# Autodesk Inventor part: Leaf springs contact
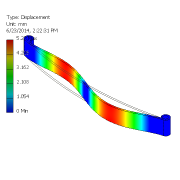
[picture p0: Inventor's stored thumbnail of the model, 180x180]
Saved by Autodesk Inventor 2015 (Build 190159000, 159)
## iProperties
Created: 2013-01
Part Number: Leaf springs contact
Material: Steel, Mild
Document SubType Name: Modeling
Designer: CADCIM
Density: 7.86 g/cm^3
Appearance: Steel
Mass: 9.78337 g
Surface Area: 26.8047 cm^2
Volume: 1.2447 cm^3
Author: CADCIM
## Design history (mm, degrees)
sketch "Sketch1"
  geometry: L1 (-48.188, 1.022)-(-47.141, 0.956); L2 (48.275, 0.799)-(47.214, 0.677); A1 r 200 centre (0, 193.649) between (-50, 0) and (50, 0); A2 r 201.033 centre (0, 193.649) between (-50.258, -1) and (50.258, -1); A3 r 1.5 centre (-49.625, 1.452) between (-48.188, 1.022) and (-50, 0); A4 r 2.533 centre (-49.625, 1.452) between (-47.141, 0.956) and (-50.258, -1); A5 r 1.5 centre (49.625, 1.452) between (50, 0) and (48.275, 0.799); A6 r 2.533 centre (49.625, 1.452) between (50.258, -1) and (47.214, 0.677); 1 further point
  constraints: 12 point on circle, 6 centre point, 4 end point, 4 tangent, 1 horizontal alignment
  dimensions: "d0" = 100 distance of A1.start A1.end; "d1" = 200 radius of A1; "d2" = 50 distance of point (0, 0) A1.start; "d3" = 1 vertical distance of A2.start A1.start; "d4" = 3 diameter of A3; "d5" = 3 diameter of A5
extrude "Extrusion1" new body sketch "Sketch1" distance "d6" = 10; taper "d7" = 0 deg
body "Solid1"
